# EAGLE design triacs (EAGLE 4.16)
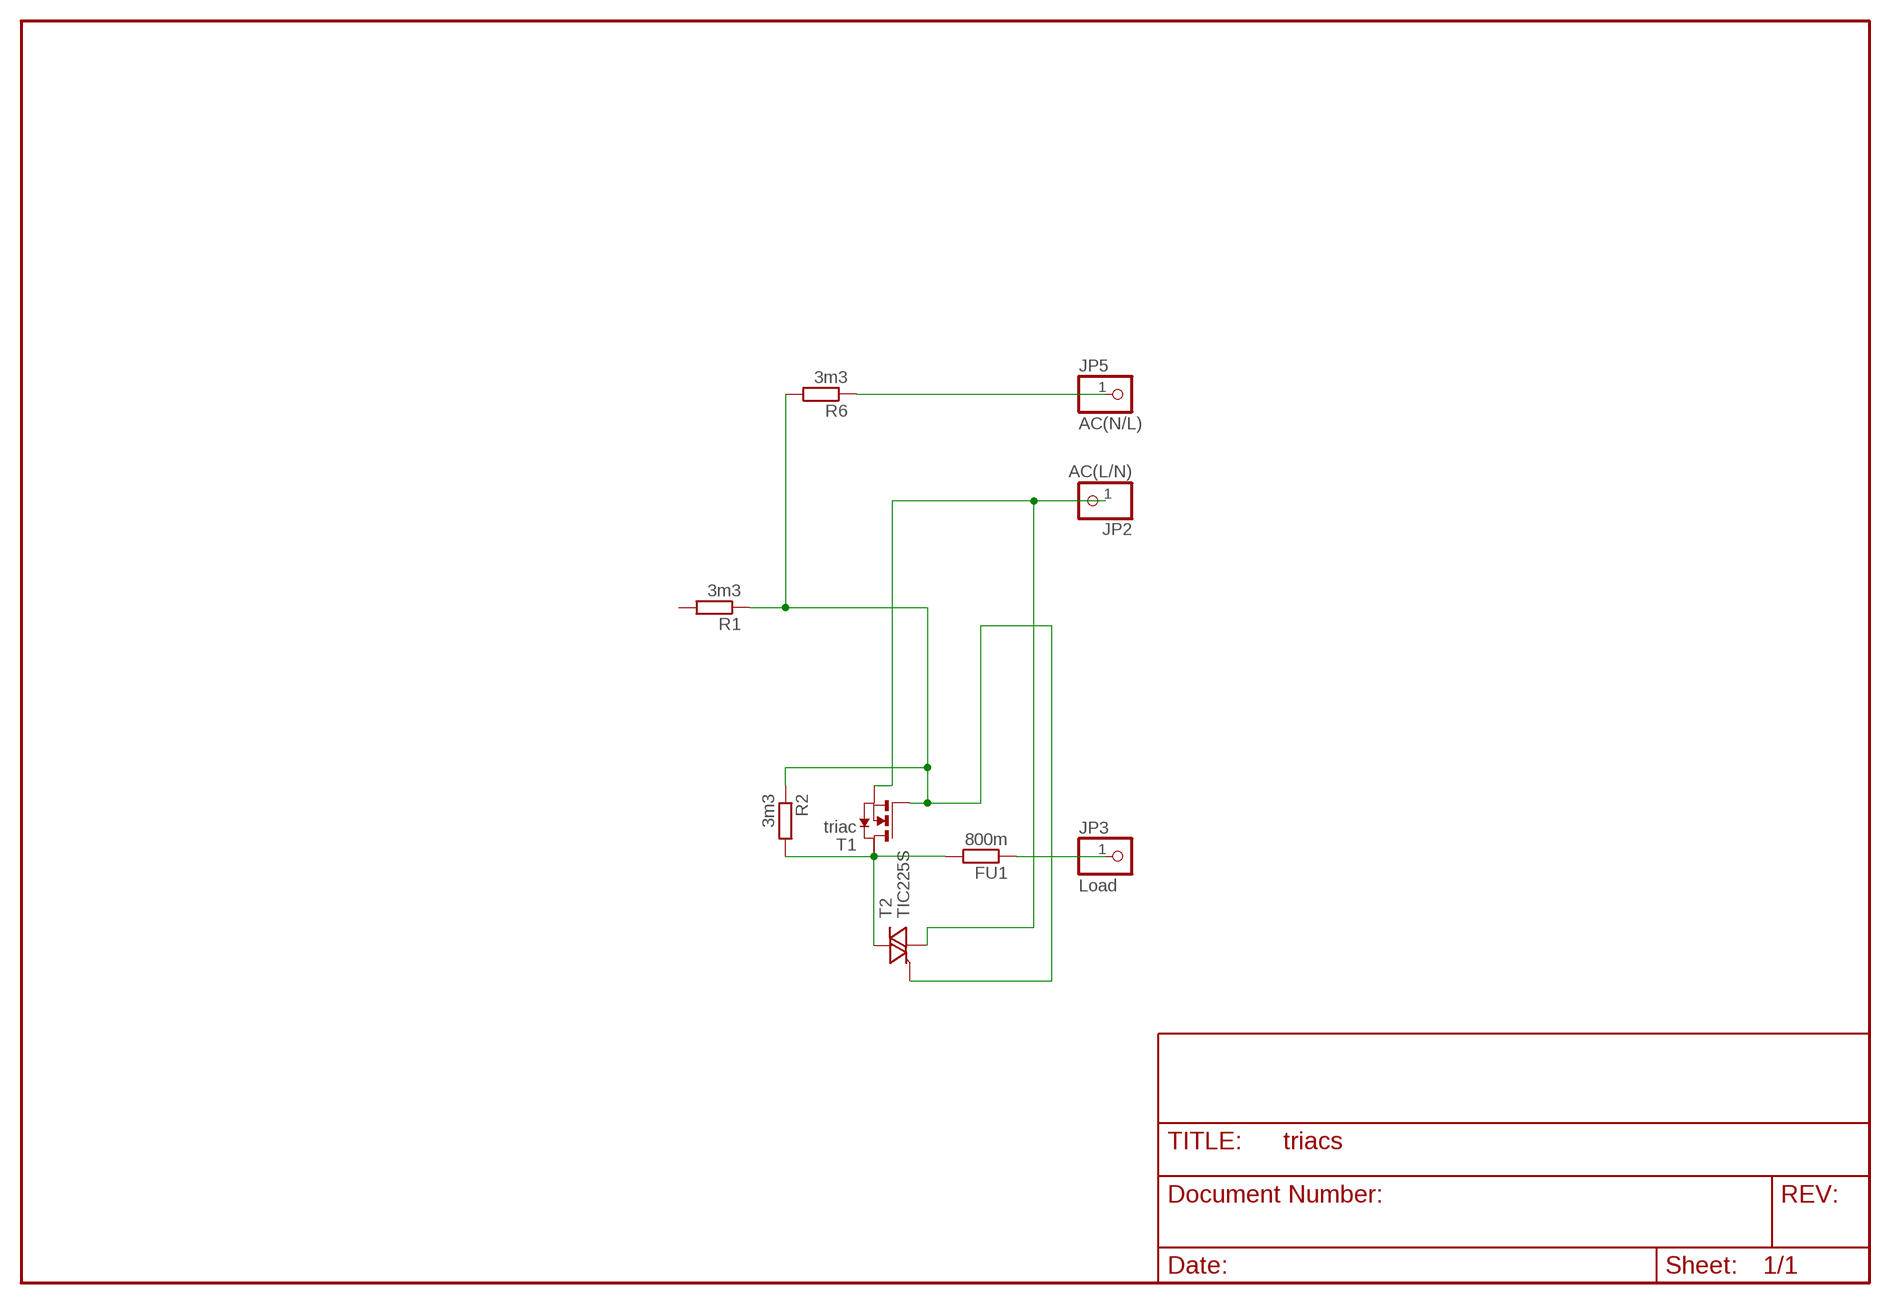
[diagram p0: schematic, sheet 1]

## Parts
FU1  800m  R-EU_0204/5  [0204/5]
JP2  AC(L/N)  PINHD-1X1  [1X01]
JP3  Load  PINHD-1X1  [1X01]
JP5  AC(N/L)  PINHD-1X1  [1X01]
R1  3m3  R-EU_0207/10  [0207/10]
R2  3m3  R-EU_0207/10  [0207/10]
R6  3m3  R-EU_0207/15  [0207/15]
T1  triac  NMOSSOT223  [SOT223]
T2  TIC225S  [TO220DS]

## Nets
AC(N): JP5.1 R6.1
N$4: R1.1 R2.1 R6.2 T1.1(G) T2.G
N$18: FU1.1 JP3.1
N$19: FU1.2 R2.2 T1.2(D) T2.A2
N$23: JP2.1 T1.3(S) T2.A1
Unconnected: R1.2 T1.4(D2)

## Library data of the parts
FU1 R1 R2 R6 = rcl:R-EU_: RESISTOR, European symbol
JP2 JP3 JP5 = pinhead:PINHD-1X1: PIN HEADER
T1 = zetex:NMOSSOT223: MOS FET
T2 = triac:TIC225S: TRIAC

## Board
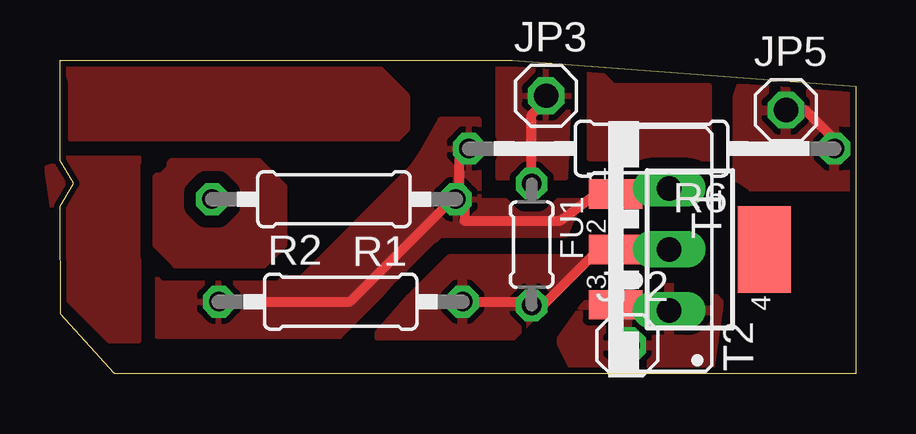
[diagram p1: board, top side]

Size 33.17 x 13.08 mm. Coordinates in mm from the lower left corner, seen from the top.
Outline: 33.17,0.01 2.29,0 2.29,0.01 0.04,2.48 0,6.99 0.57,7.94 0,8.89 0,13.08 15.18,13.08 18.86,13.08 33.17,12 33.17,0.01
Copper layers (1*16): Top 0.035mm / dielectric 1.5mm / Bottom 0.035mm
Design rules "default": minimum track width 10mil, minimum drill 24mil, track to track 20mil, track to pad 20mil, pad to pad 20mil, via to via 20mil, smd to smd 8mil, copper to edge 10mil, drill to drill 8mil, minimum pad ring 10mil, minimum via ring 8mil, stop-mask expansion 4mil, vias tented up to drill 0mil, thermal gap 10mil

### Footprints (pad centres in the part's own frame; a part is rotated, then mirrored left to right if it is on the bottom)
0204/5 = drill 0.813 octagon: 1 -2.54,0; 2 2.54,0
1X01 = drill 1.016 octagon: 1 0,0
0207/10 = drill 0.813 octagon: 1 -5.08,0; 2 5.08,0
0207/15 = drill 0.813 octagon: 1 -7.62,0; 2 7.62,0
SOT223 = smd 1.219 x 2.235: 1 -2.311,-3.099; 2 0,-3.099; 3 2.311,-3.099 | smd 3.6 x 2.2: 4 0,3.099
TO220DS = drill 1.016 long: A1 -2.54,-2.54; A2 0,-2.54; G 2.54,-2.54

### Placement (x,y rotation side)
FU1  19.66,5.39 270 top
JP2  23.66,1.19 0 top
JP3  20.26,11.59 0 top
JP5  30.26,10.99 0 top
R1  11.42,7.28 180 top
R2  11.7,3.01 0 top
R6  24.66,9.39 180 top
T1  26.26,5.19 270 top
T2  22.86,5.19 90 top

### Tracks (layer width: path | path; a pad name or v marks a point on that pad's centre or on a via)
AC(N)
  Top 0.406: R6.1 32.28,9.41 32.46,9.59 31.06,10.99 JP5.1
  pour Top: 28.46,12.19 32.46,11.79 33.06,11.59 33.06,7.79 28.86,7.79 28.26,8.19 28.26,11.59
N$1
  pour Top: 4.66,8.79 8.26,8.79 9.26,7.79 9.26,5.39 8.46,4.59 4.86,4.59 4.06,5.39 4.06,8.19 4.26,8.19 4.66,8.59
N$2
  pour Top (rank 2): 0.26,12.79 13.26,12.79 14.46,11.59 14.46,10.19 14.06,9.79 0.46,9.79 0.46,12.19
N$3
  pour Top (rank 2): 0.26,8.99 3.26,8.99 3.26,1.39 2.06,1.39 0.26,3.19 -0.54,8.59 0.06,8.79
N$4
  Top 0.406: 16.66,7.59 16.5,7.43 R1.1 16.5,7.35 16.46,7.39 12.08,3.01 R2.1 | 16.66,7.59 16.86,7.39 16.86,6.39 20.86,6.39 22.37,7.5 T1.1 24.97,7.5 25.26,7.79 25.32,7.73 T2.G | R6.2 17.04,9.37 16.66,8.99 16.66,7.59
  pour Top (rank 2): 4.06,4.19 4.06,1.59 11.66,1.59 15.86,5.79 21.06,5.79 21.66,7.19 17.46,7.19 17.46,10.59 15.86,10.59 15.06,9.19 14.66,8.59 10.06,3.99
N$5
  pour Top (rank 2): 22.06,12.59 22.06,8.99 27.06,8.99 27.06,11.99 23.06,11.99 22.46,12.59
N$18
  Top 0.406: JP3.1 20.46,11.59 19.66,10.79 FU1.1
  pour Top (rank 3): 18.26,12.79 18.26,8.19 21.06,8.19 21.26,12.59 18.86,12.79
N$19
  Top 0.406: R2.2 19.44,3.01 19.66,2.79 FU1.2 20.12,2.85 22.26,4.99 23.46,4.99 23.26,5.19 T1.2 24.66,5.19 24.86,4.99 25.46,4.99 25.66,5.19 T2.A2
  pour Top: 16.26,4.79 21.66,4.79 20.66,3.39 18.86,1.59 13.26,1.59 14.66,3.19
N$23
  Top 0.406: 25.46,2.59 T2.A1 25.17,2.88 T1.3 23.16,1.49 23.66,0.99 JP2.1
  pour Top (rank 2): 22.66,3.59 26.86,3.59 27.46,2.99 27.06,0.19 21.46,0.19 20.86,1.39 21.86,2.79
